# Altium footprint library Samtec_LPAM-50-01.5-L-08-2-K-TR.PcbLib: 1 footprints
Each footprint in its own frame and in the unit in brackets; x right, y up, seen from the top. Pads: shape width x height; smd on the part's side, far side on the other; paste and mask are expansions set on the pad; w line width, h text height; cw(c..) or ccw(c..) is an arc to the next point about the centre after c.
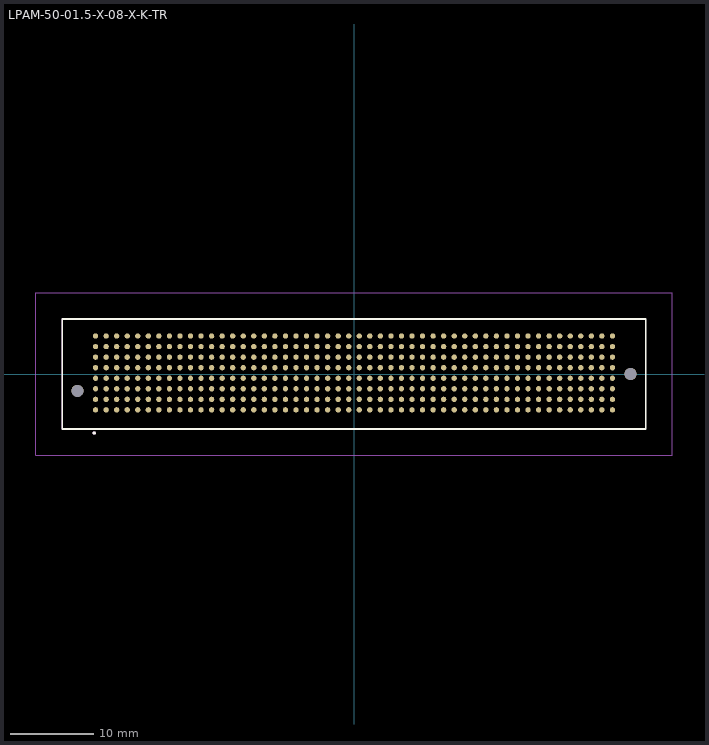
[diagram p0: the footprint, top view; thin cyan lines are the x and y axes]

## LPAM-50-01.5-X-08-X-K-TR [mm]
pads (402):
  round 0.64 smd paste-1: A01(-31.115,-4.32) A02(-29.845,-4.32) A03(-28.575,-4.32) A04(-27.305,-4.32) A05(-26.035,-4.32) A06(-24.765,-4.32) A07(-23.495,-4.32) A08(-22.225,-4.32) A09(-20.955,-4.32) A10(-19.685,-4.32) A11(-18.415,-4.32) A12(-17.145,-4.32) A13(-15.875,-4.32) A14(-14.605,-4.32) A15(-13.335,-4.32) A16(-12.065,-4.32) A17(-10.795,-4.32) A18(-9.525,-4.32) A19(-8.255,-4.32) A20(-6.985,-4.32) A21(-5.715,-4.32) A22(-4.445,-4.32) A23(-3.175,-4.32) A24(-1.905,-4.32) A25(-0.635,-4.32) A26(0.635,-4.32) A27(1.905,-4.32) A28(3.175,-4.32) A29(4.445,-4.32) A30(5.715,-4.32) A31(6.985,-4.32) A32(8.255,-4.32) A33(9.525,-4.32) A34(10.795,-4.32) A35(12.065,-4.32) A36(13.335,-4.32) A37(14.605,-4.32) A38(15.875,-4.32) A39(17.145,-4.32) A40(18.415,-4.32) A41(19.685,-4.32) A42(20.955,-4.32) A43(22.225,-4.32) A44(23.495,-4.32) A45(24.765,-4.32) A46(26.035,-4.32) A47(27.305,-4.32) A48(28.575,-4.32) A49(29.845,-4.32) A50(31.115,-4.32) B01(-31.115,-3.05) B02(-29.845,-3.05) B03(-28.575,-3.05) B04(-27.305,-3.05) B05(-26.035,-3.05) B06(-24.765,-3.05) B07(-23.495,-3.05) B08(-22.225,-3.05) B09(-20.955,-3.05) B10(-19.685,-3.05) B11(-18.415,-3.05) B12(-17.145,-3.05) B13(-15.875,-3.05) B14(-14.605,-3.05) B15(-13.335,-3.05) B16(-12.065,-3.05) B17(-10.795,-3.05) B18(-9.525,-3.05) B19(-8.255,-3.05) B20(-6.985,-3.05) B21(-5.715,-3.05) B22(-4.445,-3.05) B23(-3.175,-3.05) B24(-1.905,-3.05) B25(-0.635,-3.05) B26(0.635,-3.05) B27(1.905,-3.05) B28(3.175,-3.05) B29(4.445,-3.05) B30(5.715,-3.05) B31(6.985,-3.05) B32(8.255,-3.05) B33(9.525,-3.05) B34(10.795,-3.05) B35(12.065,-3.05) B36(13.335,-3.05) B37(14.605,-3.05) B38(15.875,-3.05) B39(17.145,-3.05) B40(18.415,-3.05) B41(19.685,-3.05) B42(20.955,-3.05) B43(22.225,-3.05) B44(23.495,-3.05) B45(24.765,-3.05) B46(26.035,-3.05) B47(27.305,-3.05) B48(28.575,-3.05) B49(29.845,-3.05) B50(31.115,-3.05) C01(-31.115,-1.78) C02(-29.845,-1.78) C03(-28.575,-1.78) C04(-27.305,-1.78) C05(-26.035,-1.78) C06(-24.765,-1.78) C07(-23.495,-1.78) C08(-22.225,-1.78) C09(-20.955,-1.78) C10(-19.685,-1.78) C11(-18.415,-1.78) C12(-17.145,-1.78) C13(-15.875,-1.78) C14(-14.605,-1.78) C15(-13.335,-1.78) C16(-12.065,-1.78) C17(-10.795,-1.78) C18(-9.525,-1.78) C19(-8.255,-1.78) C20(-6.985,-1.78) C21(-5.715,-1.78) C22(-4.445,-1.78) C23(-3.175,-1.78) C24(-1.905,-1.78) C25(-0.635,-1.78) C26(0.635,-1.78) C27(1.905,-1.78) C28(3.175,-1.78) C29(4.445,-1.78) C30(5.715,-1.78) C31(6.985,-1.78) C32(8.255,-1.78) C33(9.525,-1.78) C34(10.795,-1.78) C35(12.065,-1.78) C36(13.335,-1.78) C37(14.605,-1.78) C38(15.875,-1.78) C39(17.145,-1.78) C40(18.415,-1.78) C41(19.685,-1.78) C42(20.955,-1.78) C43(22.225,-1.78) C44(23.495,-1.78) C45(24.765,-1.78) C46(26.035,-1.78) C47(27.305,-1.78) C48(28.575,-1.78) C49(29.845,-1.78) C50(31.115,-1.78) D01(-31.115,-0.51) D02(-29.845,-0.51) D03(-28.575,-0.51) D04(-27.305,-0.51) D05(-26.035,-0.51) D06(-24.765,-0.51) D07(-23.495,-0.51) D08(-22.225,-0.51) D09(-20.955,-0.51) D10(-19.685,-0.51) D11(-18.415,-0.51) D12(-17.145,-0.51) D13(-15.875,-0.51) D14(-14.605,-0.51) D15(-13.335,-0.51) D16(-12.065,-0.51) D17(-10.795,-0.51) D18(-9.525,-0.51) D19(-8.255,-0.51) D20(-6.985,-0.51) D21(-5.715,-0.51) D22(-4.445,-0.51) D23(-3.175,-0.51) D24(-1.905,-0.51) D25(-0.635,-0.51) D26(0.635,-0.51) D27(1.905,-0.51) D28(3.175,-0.51) D29(4.445,-0.51) D30(5.715,-0.51) D31(6.985,-0.51) D32(8.255,-0.51) D33(9.525,-0.51) D34(10.795,-0.51) D35(12.065,-0.51) D36(13.335,-0.51) D37(14.605,-0.51) D38(15.875,-0.51) D39(17.145,-0.51) D40(18.415,-0.51) D41(19.685,-0.51) D42(20.955,-0.51) D43(22.225,-0.51) D44(23.495,-0.51) D45(24.765,-0.51) D46(26.035,-0.51) D47(27.305,-0.51) D48(28.575,-0.51) D49(29.845,-0.51) D50(31.115,-0.51) E01(-31.115,0.76) E02(-29.845,0.76) E03(-28.575,0.76) E04(-27.305,0.76) E05(-26.035,0.76) E06(-24.765,0.76) E07(-23.495,0.76) E08(-22.225,0.76) E09(-20.955,0.76) E10(-19.685,0.76) E11(-18.415,0.76) E12(-17.145,0.76) E13(-15.875,0.76) E14(-14.605,0.76) E15(-13.335,0.76) E16(-12.065,0.76) E17(-10.795,0.76) E18(-9.525,0.76) E19(-8.255,0.76) E20(-6.985,0.76) E21(-5.715,0.76) E22(-4.445,0.76) E23(-3.175,0.76) E24(-1.905,0.76) E25(-0.635,0.76) E26(0.635,0.76) E27(1.905,0.76) E28(3.175,0.76) E29(4.445,0.76) E30(5.715,0.76) E31(6.985,0.76) E32(8.255,0.76) E33(9.525,0.76) E34(10.795,0.76) E35(12.065,0.76) E36(13.335,0.76) E37(14.605,0.76) E38(15.875,0.76) E39(17.145,0.76) E40(18.415,0.76) E41(19.685,0.76) E42(20.955,0.76) E43(22.225,0.76) E44(23.495,0.76) E45(24.765,0.76) E46(26.035,0.76) E47(27.305,0.76) E48(28.575,0.76) E49(29.845,0.76) E50(31.115,0.76) F01(-31.115,2.03) F02(-29.845,2.03) F03(-28.575,2.03) F04(-27.305,2.03) F05(-26.035,2.03) F06(-24.765,2.03) F07(-23.495,2.03) F08(-22.225,2.03) F09(-20.955,2.03) F10(-19.685,2.03) F11(-18.415,2.03) F12(-17.145,2.03) F13(-15.875,2.03) F14(-14.605,2.03) F15(-13.335,2.03) F16(-12.065,2.03) F17(-10.795,2.03) F18(-9.525,2.03) F19(-8.255,2.03) F20(-6.985,2.03) F21(-5.715,2.03) F22(-4.445,2.03) F23(-3.175,2.03) F24(-1.905,2.03) F25(-0.635,2.03) F26(0.635,2.03) F27(1.905,2.03) F28(3.175,2.03) F29(4.445,2.03) F30(5.715,2.03) F31(6.985,2.03) F32(8.255,2.03) F33(9.525,2.03) F34(10.795,2.03) F35(12.065,2.03) F36(13.335,2.03) F37(14.605,2.03) F38(15.875,2.03) F39(17.145,2.03) F40(18.415,2.03) F41(19.685,2.03) F42(20.955,2.03) F43(22.225,2.03) F44(23.495,2.03) F45(24.765,2.03) F46(26.035,2.03) F47(27.305,2.03) F48(28.575,2.03) F49(29.845,2.03) F50(31.115,2.03) G01(-31.115,3.3) G02(-29.845,3.3) G03(-28.575,3.3) G04(-27.305,3.3) G05(-26.035,3.3) G06(-24.765,3.3) G07(-23.495,3.3) G08(-22.225,3.3) G09(-20.955,3.3) G10(-19.685,3.3) G11(-18.415,3.3) G12(-17.145,3.3) G13(-15.875,3.3) G14(-14.605,3.3) G15(-13.335,3.3) G16(-12.065,3.3) G17(-10.795,3.3) G18(-9.525,3.3) G19(-8.255,3.3) G20(-6.985,3.3) G21(-5.715,3.3) G22(-4.445,3.3) G23(-3.175,3.3) G24(-1.905,3.3) G25(-0.635,3.3) G26(0.635,3.3) G27(1.905,3.3) G28(3.175,3.3) G29(4.445,3.3) G30(5.715,3.3) G31(6.985,3.3) G32(8.255,3.3) G33(9.525,3.3) G34(10.795,3.3) G35(12.065,3.3) G36(13.335,3.3) G37(14.605,3.3) G38(15.875,3.3) G39(17.145,3.3) G40(18.415,3.3) G41(19.685,3.3) G42(20.955,3.3) G43(22.225,3.3) G44(23.495,3.3) G45(24.765,3.3) G46(26.035,3.3) G47(27.305,3.3) G48(28.575,3.3) G49(29.845,3.3) G50(31.115,3.3) H01(-31.115,4.57) H02(-29.845,4.57) H03(-28.575,4.57) H04(-27.305,4.57) H05(-26.035,4.57) H06(-24.765,4.57) H07(-23.495,4.57) H08(-22.225,4.57) H09(-20.955,4.57) H10(-19.685,4.57) H11(-18.415,4.57) H12(-17.145,4.57) H13(-15.875,4.57) H14(-14.605,4.57) H15(-13.335,4.57) H16(-12.065,4.57) H17(-10.795,4.57) H18(-9.525,4.57) H19(-8.255,4.57) H20(-6.985,4.57) H21(-5.715,4.57) H22(-4.445,4.57) H23(-3.175,4.57) H24(-1.905,4.57) H25(-0.635,4.57) H26(0.635,4.57) H27(1.905,4.57) H28(3.175,4.57) H29(4.445,4.57) H30(5.715,4.57) H31(6.985,4.57) H32(8.255,4.57) H33(9.525,4.57) H34(10.795,4.57) H35(12.065,4.57) H36(13.335,4.57) H37(14.605,4.57) H38(15.875,4.57) H39(17.145,4.57) H40(18.415,4.57) H41(19.685,4.57) H42(20.955,4.57) H43(22.225,4.57) H44(23.495,4.57) H45(24.765,4.57) H46(26.035,4.57) H47(27.305,4.57) H48(28.575,4.57) H49(29.845,4.57) H50(31.115,4.57)
  round 1.45 hole 1.45 unplated: MH1(-33.3,-2.03) MH2(33.3,0)
Top Overlay:
  circle w0.2: c-31.278,-7.114 r0.1
  lines w0.2: -35.13,-6.63 35.13,-6.63 35.13,6.63 -35.13,6.63 -35.13,-6.63
Top Paste:
  drawing of 400 lines, arcs and shapes, not listed
Mechanical 13:
  circle w0.2: c-31.278,-7.114 r0.1
  lines w0.1: -35.13,-6.63 35.13,-6.63 35.13,6.63 -35.13,6.63 -35.13,-6.63
Mechanical 15:
  lines w0.05: -38.31,-9.81 -38.31,9.81 38.31,9.81 38.31,-9.81 -38.31,-9.81
3D body "LPAM-50-01.5-L-08-2-K-TR.stp": height 4.43, standoff -1.16, extent -35.128,-6.995 35.128,6.995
